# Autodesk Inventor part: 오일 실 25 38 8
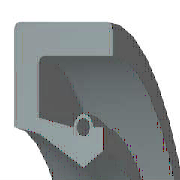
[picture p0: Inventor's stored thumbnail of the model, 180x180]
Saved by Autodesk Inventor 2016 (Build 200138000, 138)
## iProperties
IsCustomPart: 1
Created: 2012-02
Part Number: 오일 실 25 38 8
Material: 고무
Description: 오일-실
Document SubType Name: Modeling
Standard: KS B 2804
Designer: mduedu
Standards Organization: KS
Language: ko-KR
Size Designation: S - 25 38 8
Categories: <MemberInstance><Categories><Category DisplayName="샤프트 부품" InternalName="7f7aeb1f-a693-4053-b835-cee3144e0d98" Mnemonic="SHFT"><Category DisplayName="실링" Intern
Density: 0.93 g/cm^3
Appearance: 고무 - 검은색 - 버전 1.1
Author: mduedu
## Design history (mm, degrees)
revolve "본체" stored, may be unused: angle "d17" = 90 deg
revolve "스프링1" stored, may be unused: angle "d18" = 90 deg
body "Solid1"
sketch "스케치1"
  geometry: L1 (0, 19)-(8, 19); L2 (8, 19)-(8, 17.75); L3 (8, 17.75)-(1.75, 17.75); L4 (0, 19)-(0, 14.6); L5 (0, 14.6)-(1.75, 14.25); L6 (1.75, 14.25)-(4.9, 12.5); L7 (4.9, 12.5)-(0, 12.5); L8 (6.3, 13.375)-(6.3, 14.6); L9 (0, 0)-(9.586, 0) reference; L10 (4.9, 12.5)-(6.3, 13.375); L11 (0, 18)-(0, -3) reference; L12 (-1.917, 0)-(11.503, 0) reference; L13 (4.2, 14.6)-(1.75, 15.09); L14 (1.75, 15.09)-(1.75, 17.75); L15 (6.3, 14.6)-(5.6, 14.6); C1 r 0.455 at (4.9, 14.6); A1 r 0.7 centre (4.9, 14.6) between (5.6, 14.6) and (4.2, 14.6)
  constraints: 26 end point, 5 horizontal alignment, 4 perpendicular, 2 centre point, 2 collinear, 2 horizontal, 2 parallel, 2 point on circle, 2 point on line, 2 vertical alignment, 1 coincident
  dimensions: "d0" = 38 diameter of L1 L9 (= SD2); "d1" = 26.75 diameter of L8.start L9 (= ABDM); "d2" = 1.25 distance of L1.end L2.end (computed from SD); "d3" = 0.91 diameter of C1 (= SPDI); "d4" = 1.4 diameter of A1 (= SPDA); "d5" = 25 diameter of L6.end L9 (= NND); "d6" = 28.5 diameter of L5.end L9 (= TKDM); "d7" = 29.2 diameter of L4.end L9 (= HLDM); "d8" = 4.9 distance from line of C1.centre L4 (= SPDST); "d9" = 6.3 distance between parallel lines of L8 L4 (= SDI); "d10" = 8 distance between parallel lines of L2 L4 (= SWDT); "d12" = 1.75 distance between parallel lines of L14 L4 (= SD)
fillet "모깎기1" dims "d11" = 0.5 (= RR)
other parameters: "SD2" = 38 [user parameter; used in 1 equation term], "SWDT" = 8 [user parameter; used in 1 equation term], "RR" = 0.5 [user parameter; used in 1 equation term], "SD" = 1.75 [user parameter; used in 2 equation terms], "NND" = 25 [user parameter; used in 1 equation term], "SPDA" = 1.4 [user parameter; used in 1 equation term], "SPDI" = 0.91 [user parameter; used in 1 equation term], "TKDM" = 28.5 [user parameter; used in 1 equation term], "HLDM" = 29.2 [user parameter; used in 1 equation term], "ABDM" = 26.75 [user parameter; used in 1 equation term], "SDI" = 6.3 [user parameter; used in 1 equation term], "SPDST" = 4.9 [user parameter; used in 1 equation term], "d13" = 0, "d14" = 0, "d15" = 0, "LAB" = 0.35 [user parameter]
